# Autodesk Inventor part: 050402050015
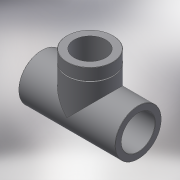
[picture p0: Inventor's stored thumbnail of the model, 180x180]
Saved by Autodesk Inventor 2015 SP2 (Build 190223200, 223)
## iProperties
Created: 2017-10
Part Number: 050402050015
Material: Generic
Description: PLASSON NOT ACTIVE- TEE THR-CEM REINF. P 50-1.1/2"
Document SubType Name: Modeling
Designer: KIM
Density: 1 g/cm^3
Appearance: Default
Author: KIM
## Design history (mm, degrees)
derived "057402.ipt"
feature "Solid1::057402.ipt"
feature "Solid2::057402.ipt"
tag "TaggingFeature1"
body "Solid1"
other parameters: "d0" = 118, "d1" = 62, "d2" = 31, "d5" = 40.3605, "d7" = 0.44845, "d8" = 31, "d9" = 59, "d10" = 62, "d15" = 0, "d18" = 44.845, "d24" = 0.44845, "d30" = 44.845, "d31" = 22, "d32" = 0, "d33" = 40.3605, "d35" = 0, "d37" = 0.5, "d38" = 0.5, "d39" = 14.75, "d40" = 62, "G_" = 44.845, "E_" = 62, "H_" = 118, "lt_" = 22, "l_" = 31, "h_" = 59
